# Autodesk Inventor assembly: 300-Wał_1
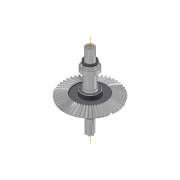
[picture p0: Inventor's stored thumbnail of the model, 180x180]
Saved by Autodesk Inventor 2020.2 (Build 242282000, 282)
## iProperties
Created: 2015-05
Part Number: 300-Wał_1
Document SubType Name: Assembly
Designer: F.Stasiak
Manager: www.cadconsulting.pl
Company: Fabian Stasiak CAD Consulting
Author: F.Stasiak
Subject: Zbiór ćwiczeń. Autodesk Inventor 2020. Kurs podstawowy
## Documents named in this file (8)
- C:\2020_Kurs_podstawowy\R7 Prezentacje\Komponenty\300-Wał_1.iam
- C:\2020_Kurs_podstawowy\R7 Prezentacje\Komponenty\V_123-0050.ipt
- C:\2020_Kurs_podstawowy\R7 Prezentacje\Komponenty\V_123-0040.ipt
- C:\2020_Kurs_podstawowy\R7 Prezentacje\Komponenty\V_123-0080.ipt
- C:\2020_Kurs_podstawowy\R7 Prezentacje\Komponenty\V_SKF 6005.ipt
- C:\2020_Kurs_podstawowy\R7 Prezentacje\Komponenty\pl-PL\DIN 3760 A\V_22x35x7.ipt
- C:\2020_Kurs_podstawowy\R7 Prezentacje\Komponenty\pl-PL\DIN 3760 A\V_25x35x7.ipt
- C:\2020_Kurs_podstawowy\R7 Prezentacje\Komponenty\pl-PL\DIN 6885  A\V_22 - 30-8x7-28.ipt
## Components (8 placed, 7 different names)
1. Wał:1
2. Przekładnie zębate stożkowe 15/51, 3_1:1
3. V_123-0080:1
4. Łożysko SKF 6005:1
5. Łożysko SKF 6005:2
6. DIN 3760 A A - 22 x 35 x 7 - NBR:1
7. DIN 3760 A A - 25 x 35 x 7 - NBR:1
8. DIN 6885  A A 8 x 7 x 28:1
